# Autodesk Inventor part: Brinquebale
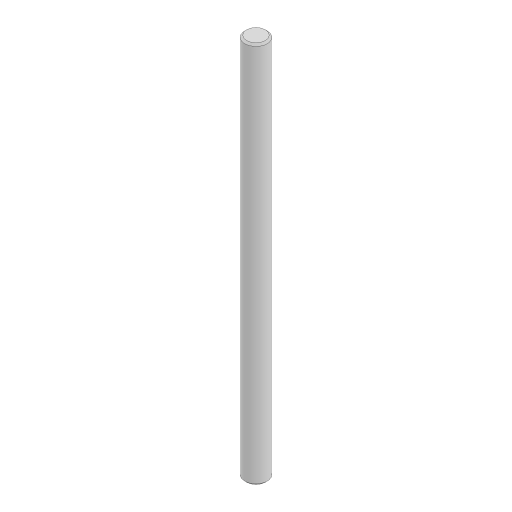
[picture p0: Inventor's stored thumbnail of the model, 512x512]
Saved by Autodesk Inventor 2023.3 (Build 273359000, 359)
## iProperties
Created: 2024-11
Part Number: Brinquebale
Material: Générique
Description: STEP AP203
Document SubType Name: Modeling
Designer: Thier
Density: 1 g/cm^3
Appearance: Par défaut
Title: Brinquebale.STEP
Revision Number: ANY
Sending System: SolidWorks 2017
Preprocessor: SwSTEP 2.0
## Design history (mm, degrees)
feature "Chanfrein1"
node "Solide1"
